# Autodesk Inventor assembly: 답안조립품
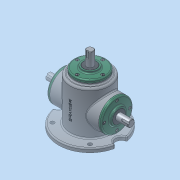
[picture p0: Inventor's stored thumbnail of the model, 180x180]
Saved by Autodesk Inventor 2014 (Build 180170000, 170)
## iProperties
Created: 2018-04
Part Number: 답안조립품
Document SubType Name: Assembly
Designer: net
Author: net
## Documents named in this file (16)
- C:\Users\net\Desktop\480407V1024\답안조립품.iam
- C:\Users\net\Desktop\480407V1024\본체.ipt
- C:\Users\net\Desktop\480407V1024\메인 베벨기어.ipt
- C:\Users\net\Desktop\480407V1024\메인 축.ipt
- 메인 축.ipt
- C:\Users\net\Desktop\480407V1024\베어링 6203.ipt
- C:\Users\net\Desktop\480407V1024\볼트 M4.ipt
- 볼트 M4.ipt
- C:\Users\net\Desktop\480407V1024\서브 베벨기어.ipt
- C:\Users\net\Desktop\480407V1024\서브 축.ipt
- 서브 축.ipt
- C:\Users\net\Desktop\480407V1024\오일 실.ipt
- 오일 실.ipt
- C:\Users\net\Desktop\480407V1024\커버.ipt
- C:\Users\net\Desktop\480407V1024\키 4x4.ipt
- C:\Users\net\Desktop\480407V1024\키 5x5.ipt
## Named parameters: d15_d13 = 0, d16_d14 = 0, d17_d13 = 0, d18_d14 = 0, d36_d2 = 0, d37_d3 = 0, d38_d4 = 0, d39_d8 = 0, d40_d9 = 0, d41_d10 = 0, d42_d11 = 0, d43_d12 = 0
